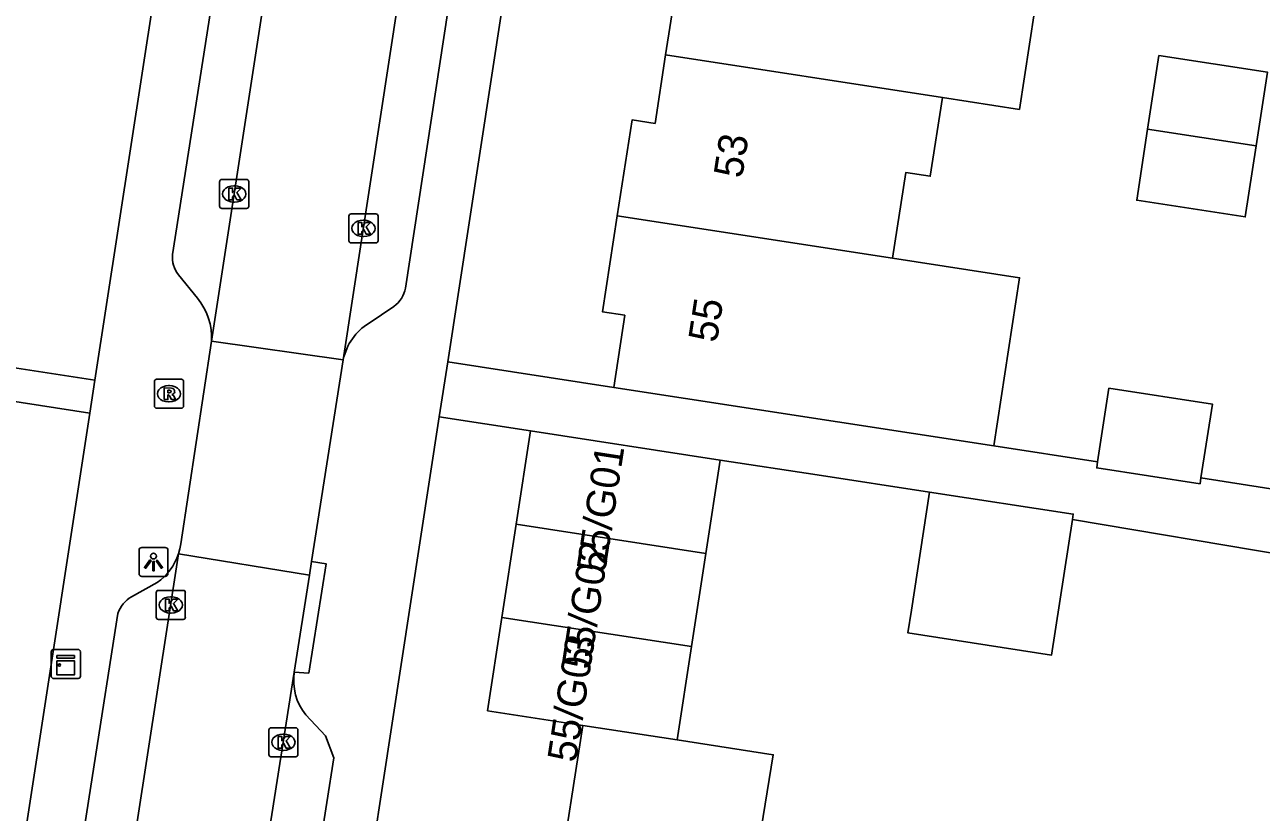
# Model space of a CAD drawing. Extents: x 161486 to 162249, y 379484 to 380829.
# Drawn here: x 162006.52 to 162049.09, y 380555.03 to 380582.15 of the extents above; entities that cross this region are included whole.
import ezdxf

# ---------------------------------------------------------------- set-up
doc = ezdxf.new("R2010")
doc.units = 0
for name, color, linetype in [('IMGEO_Kast', 7, 'Continuous'), ('IMGEO_Kolk', 7, 'Continuous'), ('IMGEO_Lichtpunt', 7, 'Continuous'), ('IMGEO_Pand', 7, 'Continuous'), ('IMGEO_Pand_nummerreeks', 7, 'Continuous'), ('IMGEO_Rijbaan_lokaal_open', 7, 'Continuous'), ('IMGEO_Rioolput', 7, 'Continuous'), ('IMGEO_Voetpad_open', 7, 'Continuous')]:
    doc.layers.add(name, color=color, linetype=linetype)

msp = doc.modelspace()

# ---------------------------------------------------------------- linework, layer by layer
at = {"layer": 'IMGEO_Kast'}
for p, q in [((162007.436, 380559.713), (162007.436, 380560.554)), ((162007.436, 380560.554), (162007.436, 380559.713)), ((162007.511, 380560.638), (162008.352, 380560.638)), ((162008.352, 380560.638), (162007.511, 380560.638)), ((162008.436, 380560.563), (162008.436, 380559.722)), ((162008.436, 380559.722), (162008.436, 380560.563)), ((162008.361, 380559.638), (162007.52, 380559.638)), ((162007.52, 380559.638), (162008.361, 380559.638))]:
    msp.add_line(p, q, dxfattribs=at)
for points in [[(162007.631, 380560.428), (162008.231, 380560.428), (162008.231, 380560.343), (162007.631, 380560.343), (162007.631, 380560.428)], [(162007.631, 380560.253), (162008.231, 380560.253), (162008.231, 380559.764), (162007.631, 380559.764), (162007.631, 380560.253)]]:
    msp.add_lwpolyline(points, dxfattribs=at)
msp.add_circle((162007.715, 380560.102), 0.0377, dxfattribs=at)
for centre, start, end in [((162007.514, 380560.56), 92.4484, 184.2845), ((162007.514, 380560.56), 92.4484, 184.2845), ((162008.358, 380560.56), 2.4484, 94.2845), ((162008.358, 380560.56), 2.4484, 94.2845), ((162007.514, 380559.716), 182.4484, 274.2845), ((162007.514, 380559.716), 182.4484, 274.2845), ((162008.358, 380559.716), 272.4484, 4.2845), ((162008.358, 380559.716), 272.4484, 4.2845)]:
    msp.add_arc(centre, 0.0779, start, end, dxfattribs=at)
at = {"layer": 'IMGEO_Kolk'}
for p, q in [((162013.232, 380575.895), (162013.232, 380576.747)), ((162013.307, 380576.821), (162014.159, 380576.821)), ((162013.72, 380576.601), (162013.745, 380576.601)), ((162014.233, 380576.747), (162014.233, 380575.895)), ((162014.159, 380575.821), (162013.307, 380575.821)), ((162013.743, 380576.041), (162013.718, 380576.041)), ((162017.683, 380574.71), (162017.683, 380575.562)), ((162017.758, 380575.636), (162018.61, 380575.636)), ((162018.171, 380575.416), (162018.196, 380575.416)), ((162018.684, 380575.562), (162018.684, 380574.71)), ((162018.194, 380574.856), (162018.169, 380574.856)), ((162018.61, 380574.636), (162017.758, 380574.636)), ((162011.049, 380561.748), (162011.049, 380562.6)), ((162011.124, 380562.674), (162011.976, 380562.674)), ((162012.05, 380562.6), (162012.05, 380561.748)), ((162011.537, 380562.454), (162011.562, 380562.454)), ((162011.976, 380561.674), (162011.124, 380561.674)), ((162011.56, 380561.894), (162011.535, 380561.894)), ((162014.924, 380557.019), (162014.924, 380557.871)), ((162014.999, 380557.945), (162015.851, 380557.945)), ((162015.925, 380557.871), (162015.925, 380557.019)), ((162015.412, 380557.725), (162015.437, 380557.725)), ((162015.851, 380556.945), (162014.999, 380556.945)), ((162015.435, 380557.165), (162015.41, 380557.165))]:
    msp.add_line(p, q, dxfattribs=at)
for points in [[(162013.232, 380575.895), (162013.232, 380576.747)], [(162013.307, 380576.821), (162014.159, 380576.821)], [(162013.553, 380576.521), (162013.676, 380576.521), (162013.676, 380576.37), (162013.806, 380576.521), (162013.97, 380576.521), (162013.824, 380576.37), (162013.977, 380576.121), (162013.825, 380576.121), (162013.74, 380576.285), (162013.676, 380576.218), (162013.676, 380576.121), (162013.553, 380576.121), (162013.553, 380576.521)], [(162014.233, 380576.747), (162014.233, 380575.895)], [(162014.159, 380575.821), (162013.307, 380575.821)], [(162017.683, 380574.71), (162017.683, 380575.562)], [(162017.758, 380575.636), (162018.61, 380575.636)], [(162018.004, 380575.336), (162018.127, 380575.336), (162018.127, 380575.185), (162018.257, 380575.336), (162018.421, 380575.336), (162018.275, 380575.185), (162018.428, 380574.936), (162018.276, 380574.936), (162018.191, 380575.1), (162018.127, 380575.033), (162018.127, 380574.936), (162018.004, 380574.936), (162018.004, 380575.336)], [(162018.684, 380575.562), (162018.684, 380574.71)], [(162018.61, 380574.636), (162017.758, 380574.636)], [(162011.049, 380561.748), (162011.049, 380562.6)], [(162011.124, 380562.674), (162011.976, 380562.674)], [(162012.05, 380562.6), (162012.05, 380561.748)], [(162011.37, 380562.374), (162011.493, 380562.374), (162011.493, 380562.223), (162011.623, 380562.374), (162011.787, 380562.374), (162011.641, 380562.223), (162011.794, 380561.974), (162011.642, 380561.974), (162011.557, 380562.138), (162011.493, 380562.071), (162011.493, 380561.974), (162011.37, 380561.974), (162011.37, 380562.374)], [(162011.976, 380561.674), (162011.124, 380561.674)], [(162014.924, 380557.019), (162014.924, 380557.871)], [(162014.999, 380557.945), (162015.851, 380557.945)], [(162015.925, 380557.871), (162015.925, 380557.019)], [(162015.245, 380557.645), (162015.368, 380557.645), (162015.368, 380557.494), (162015.498, 380557.645), (162015.662, 380557.645), (162015.516, 380557.494), (162015.669, 380557.245), (162015.517, 380557.245), (162015.432, 380557.409), (162015.368, 380557.342), (162015.368, 380557.245), (162015.245, 380557.245), (162015.245, 380557.645)], [(162015.851, 380556.945), (162014.999, 380556.945)]]:
    msp.add_lwpolyline(points, dxfattribs=at)
for centre, start, end in [((162013.309, 380576.745), 91.552, 178.448), ((162013.309, 380576.745), 91.552, 178.448), ((162014.157, 380576.745), 1.552, 88.448), ((162014.157, 380576.745), 1.552, 88.448), ((162013.309, 380575.897), 181.552, 268.448), ((162013.309, 380575.897), 181.552, 268.448), ((162014.157, 380575.897), 271.552, 358.448), ((162014.157, 380575.897), 271.552, 358.448), ((162017.76, 380575.56), 91.552, 178.448), ((162017.76, 380575.56), 91.552, 178.448), ((162018.608, 380575.56), 1.552, 88.448), ((162018.608, 380575.56), 1.552, 88.448), ((162017.76, 380574.712), 181.552, 268.448), ((162017.76, 380574.712), 181.552, 268.448), ((162018.608, 380574.712), 271.552, 358.448), ((162018.608, 380574.712), 271.552, 358.448), ((162011.126, 380562.598), 91.552, 178.448), ((162011.126, 380562.598), 91.552, 178.448), ((162011.974, 380562.598), 1.552, 88.448), ((162011.974, 380562.598), 1.552, 88.448), ((162011.126, 380561.75), 181.552, 268.448), ((162011.126, 380561.75), 181.552, 268.448), ((162011.974, 380561.75), 271.552, 358.448), ((162011.974, 380561.75), 271.552, 358.448), ((162015.001, 380557.869), 91.552, 178.448), ((162015.001, 380557.869), 91.552, 178.448), ((162015.849, 380557.869), 1.552, 88.448), ((162015.849, 380557.869), 1.552, 88.448), ((162015.001, 380557.021), 181.552, 268.448), ((162015.001, 380557.021), 181.552, 268.448), ((162015.849, 380557.021), 271.552, 358.448), ((162015.849, 380557.021), 271.552, 358.448)]:
    msp.add_arc(centre, 0.0765, start, end, dxfattribs=at)
for centre, major_axis, ratio, start_param, end_param in [((162013.719, 380576.321), (-0.387, 0.002), 0.722429, 4.712389, 7.853982), ((162013.744, 380576.321), (-0.39, 0.002), 0.717154, 1.570796, 4.712389), ((162018.17, 380575.136), (-0.387, 0.002), 0.722429, 4.712389, 7.853982), ((162018.195, 380575.136), (-0.39, 0.002), 0.717154, 1.570796, 4.712389), ((162011.536, 380562.174), (-0.387, 0.002), 0.722429, 4.712389, 7.853982), ((162011.561, 380562.174), (-0.39, 0.002), 0.717154, 1.570796, 4.712389), ((162015.411, 380557.445), (-0.387, 0.002), 0.722429, 4.712389, 7.853982), ((162015.436, 380557.445), (-0.39, 0.002), 0.717154, 1.570796, 4.712389)]:
    msp.add_ellipse(centre, major_axis=major_axis, ratio=ratio, start_param=start_param, end_param=end_param, dxfattribs=at)
at = {"layer": 'IMGEO_Lichtpunt'}
for p, q in [((162010.456, 380564.056), (162010.456, 380563.249)), ((162010.456, 380564.056), (162010.456, 380563.249)), ((162011.358, 380564.151), (162010.55, 380564.151)), ((162011.358, 380564.151), (162010.55, 380564.151)), ((162011.452, 380563.249), (162011.452, 380564.056)), ((162011.452, 380563.249), (162011.452, 380564.056)), ((162010.55, 380563.155), (162011.358, 380563.155)), ((162010.55, 380563.155), (162011.358, 380563.155))]:
    msp.add_line(p, q, dxfattribs=at)
for points in [[(162010.83, 380563.72), (162010.869, 380563.692), (162010.681, 380563.43), (162010.643, 380563.457), (162010.83, 380563.72)], [(162010.932, 380563.672), (162010.979, 380563.672), (162010.979, 380563.35), (162010.932, 380563.35), (162010.932, 380563.672)], [(162011.042, 380563.692), (162011.08, 380563.719), (162011.267, 380563.457), (162011.228, 380563.429), (162011.042, 380563.692)]]:
    msp.add_lwpolyline(points, dxfattribs=at)
msp.add_circle((162010.955, 380563.854), 0.0994, dxfattribs=at)
for centre, start, end in [((162010.55, 380564.056), 90, 180), ((162010.55, 380564.056), 90, 180), ((162011.358, 380564.056), 0, 90), ((162011.358, 380564.056), 0, 90), ((162010.55, 380563.249), 180, 270), ((162010.55, 380563.249), 180, 270), ((162011.358, 380563.249), 270, 0), ((162011.358, 380563.249), 270, 360)]:
    msp.add_arc(centre, 0.0946, start, end, dxfattribs=at)
at = {"layer": 'IMGEO_Pand'}
for points in [[(162029.412, 380586.746), (162029.363, 380586.427), (162028.576, 380586.548), (162028.117, 380583.563), (162028.943, 380583.436), (162028.584, 380581.106)], [(162041.629, 380584.866), (162040.764, 380579.233), (162038.115, 380579.64)], [(162028.584, 380581.106), (162028.222, 380578.751), (162027.429, 380578.873), (162026.921, 380575.57)], [(162038.115, 380579.64), (162028.584, 380581.106)], [(162048.92, 380577.98), (162049.309, 380580.512), (162045.571, 380581.087), (162045.181, 380578.554)], [(162036.4, 380574.109), (162036.853, 380577.059), (162037.698, 380576.929), (162038.115, 380579.64)], [(162045.181, 380578.554), (162044.804, 380576.104), (162048.543, 380575.529), (162048.92, 380577.98)], [(162048.92, 380577.98), (162045.181, 380578.554)], [(162026.797, 380569.663), (162027.179, 380572.146), (162026.412, 380572.264), (162026.921, 380575.57)], [(162026.921, 380575.57), (162036.4, 380574.109)], [(162036.4, 380574.109), (162040.773, 380573.434), (162039.883, 380567.65)], [(162039.883, 380567.65), (162031.739, 380568.903), (162026.797, 380569.663)], [(162047.017, 380566.543), (162047.408, 380569.087), (162043.85, 380569.634), (162043.459, 380567.095)], [(162023.444, 380564.952), (162023.938, 380568.163)], [(162023.938, 380568.163), (162030.468, 380567.158)], [(162030.468, 380567.158), (162029.974, 380563.947)], [(162043.459, 380567.095), (162043.428, 380566.891), (162046.986, 380566.343), (162047.017, 380566.543)], [(162042.591, 380565.109), (162041.873, 380560.445), (162036.929, 380561.206), (162037.05, 380561.997), (162037.675, 380566.06)], [(162037.675, 380566.06), (162042.62, 380565.299), (162042.591, 380565.109)], [(162022.95, 380561.741), (162023.444, 380564.952)], [(162029.974, 380563.947), (162023.444, 380564.952)], [(162029.974, 380563.947), (162029.48, 380560.736)], [(162025.73, 380558.026), (162022.456, 380558.53), (162022.95, 380561.741)], [(162022.95, 380561.741), (162029.48, 380560.736)], [(162029.48, 380560.736), (162028.986, 380557.525)], [(162029.98, 380542.31), (162023.467, 380543.312), (162024.878, 380552.488), (162025.73, 380558.026)], [(162025.73, 380558.026), (162028.986, 380557.525)], [(162028.986, 380557.525), (162032.293, 380557.017), (162031.391, 380551.486)]]:
    msp.add_lwpolyline(points, dxfattribs=at)
at = {"layer": 'IMGEO_Rijbaan_lokaal_open'}
for points in [[(162012.953, 380571.252), (162023.503, 380639.839)], [(162027.966, 380638.912), (162017.489, 380570.616)], [(162011.818, 380563.929), (162011.858, 380564.099), (162011.9, 380564.273), (162012.953, 380571.252)], [(162012.953, 380571.252), (162017.489, 380570.616)], [(162017.489, 380570.616), (162016.398, 380563.665)], [(162008.586, 380543.018), (162011.818, 380563.929)], [(162016.325, 380563.195), (162011.818, 380563.929)], [(162016.398, 380563.665), (162016.325, 380563.195)], [(162016.325, 380563.195), (162015.801, 380559.859)], [(162015.801, 380559.859), (162013.037, 380542.229)]]:
    msp.add_lwpolyline(points, dxfattribs=at)
at = {"layer": 'IMGEO_Rioolput'}
for p, q in [((162010.987, 380569.016), (162010.987, 380569.868)), ((162011.062, 380569.942), (162011.914, 380569.942)), ((162011.475, 380569.722), (162011.5, 380569.722)), ((162011.988, 380569.868), (162011.988, 380569.016)), ((162011.914, 380568.942), (162011.062, 380568.942)), ((162011.498, 380569.162), (162011.473, 380569.162))]:
    msp.add_line(p, q, dxfattribs=at)
for points in [[(162010.987, 380569.016), (162010.987, 380569.868)], [(162011.062, 380569.942), (162011.914, 380569.942)], [(162011.988, 380569.868), (162011.988, 380569.016)], [(162011.576, 380569.64), (162011.324, 380569.642), (162011.324, 380569.242)], [(162011.324, 380569.242), (162011.448, 380569.242), (162011.448, 380569.404), (162011.459, 380569.404)], [(162011.502, 380569.561), (162011.448, 380569.561), (162011.448, 380569.48)], [(162011.448, 380569.48), (162011.5, 380569.48)], [(162011.506, 380569.375), (162011.577, 380569.242), (162011.717, 380569.242), (162011.652, 380569.368)], [(162011.914, 380568.942), (162011.062, 380568.942)]]:
    msp.add_lwpolyline(points, dxfattribs=at)
for centre, radius, start, end in [((162011.064, 380569.866), 0.0765, 91.552, 178.448), ((162011.064, 380569.866), 0.0765, 91.552, 178.448), ((162011.912, 380569.866), 0.0765, 1.552, 88.448), ((162011.912, 380569.866), 0.0765, 1.552, 88.448), ((162011.458, 380569.351), 0.0533, 26.0293, 88.6989), ((162011.484, 380569.669), 0.19, 274.7715, 282.9687), ((162011.508, 380569.465), 0.0964, 77.0061, 93.1865), ((162011.522, 380569.522), 0.0378, 276.6634, 79.6772), ((162011.575, 380569.53), 0.109, 350.3612, 89.416), ((162011.573, 380569.53), 0.112, 277.5842, 350.9817), ((162011.557, 380569.315), 0.108, 29.5134, 73.7905), ((162011.064, 380569.018), 0.0765, 181.552, 268.448), ((162011.064, 380569.018), 0.0765, 181.552, 268.448), ((162011.912, 380569.018), 0.0765, 271.552, 358.448), ((162011.912, 380569.018), 0.0765, 271.552, 358.448)]:
    msp.add_arc(centre, radius, start, end, dxfattribs=at)
for centre, major_axis, ratio, start_param, end_param in [((162011.474, 380569.442), (-0.387, 0.002), 0.722429, 4.712389, 7.853982), ((162011.499, 380569.442), (-0.39, 0.002), 0.717154, 1.570796, 4.712389)]:
    msp.add_ellipse(centre, major_axis=major_axis, ratio=ratio, start_param=start_param, end_param=end_param, dxfattribs=at)
at = {"layer": 'IMGEO_Voetpad_open'}
for points in [[(162021.082, 380570.54), (162034.113, 380655.414)], [(162019.94, 380641.308), (162008.935, 380569.909)], [(162023.699, 380604.072), (162024.363, 380604.007), (162019.634, 380573.078)], [(162011.61, 380574.235), (162013.209, 380584.453), (162013.891, 380584.363)], [(162012.467, 380572.733), (162011.815, 380573.536)], [(162019.23, 380572.451), (162018.375, 380571.873)], [(162008.935, 380569.909), (162001.469, 380571.06)], [(162020.791, 380568.646), (162021.082, 380570.54)], [(162026.797, 380569.663), (162021.082, 380570.54)], [(162001.293, 380569.928), (162008.76, 380568.777)], [(162008.76, 380568.777), (162008.935, 380569.909)], [(162004.779, 380542.949), (162008.76, 380568.777)], [(162020.791, 380568.646), (162016.576, 380541.193)], [(162023.938, 380568.163), (162020.791, 380568.646)], [(162043.459, 380567.095), (162039.883, 380567.65)], [(162037.675, 380566.06), (162033.806, 380566.655), (162030.468, 380567.158)], [(162052.202, 380565.738), (162047.017, 380566.543)], [(162049.945, 380563.869), (162042.591, 380565.109)], [(162016.398, 380563.665), (162016.899, 380563.586), (162016.301, 380559.828), (162015.801, 380559.859)], [(162010.202, 380562.452), (162011.077, 380562.943)], [(162007.238, 380545.927), (162008.908, 380556.667), (162009.726, 380561.874)], [(162016.198, 380558.385), (162016.88, 380557.665), (162017.16, 380556.912), (162015.237, 380544.609)]]:
    msp.add_lwpolyline(points, dxfattribs=at)
for centre, radius, start, end in [((162012.598, 380574.145), 0.992, 174.7994, 217.8909), ((162010.807, 380571.368), 2.15, 356.91, 39.4252), ((162018.615, 380573.291), 1.041, 306.2208, 348.1888), ((162019.373, 380570.229), 1.924, 121.2608, 168.3828), ((162009.961, 380564.553), 1.959, 304.7257, 341.423), ((162010.714, 380561.546), 1.041, 119.4485, 161.6066), ((162017.679, 380559.574), 1.899, 171.3802, 218.7679)]:
    msp.add_arc(centre, radius, start, end, dxfattribs=at)

# ---------------------------------------------------------------- texts
at = {"layer": 'IMGEO_Pand_nummerreeks'}
for s, rotation, p in [('53', 81.2557, (162031.219, 380576.834)), ('55', 81.2557, (162030.348, 380571.176)), ('55/G01', 81.2538, (162026.501, 380563.251)), ('55/G02', 81.2538, (162025.989, 380559.925)), ('55/G03', 81.2511, (162025.496, 380556.721))]:
    msp.add_text(s, height=1, rotation=rotation, dxfattribs=at).set_placement(p)

doc.saveas('drawing.dxf')
